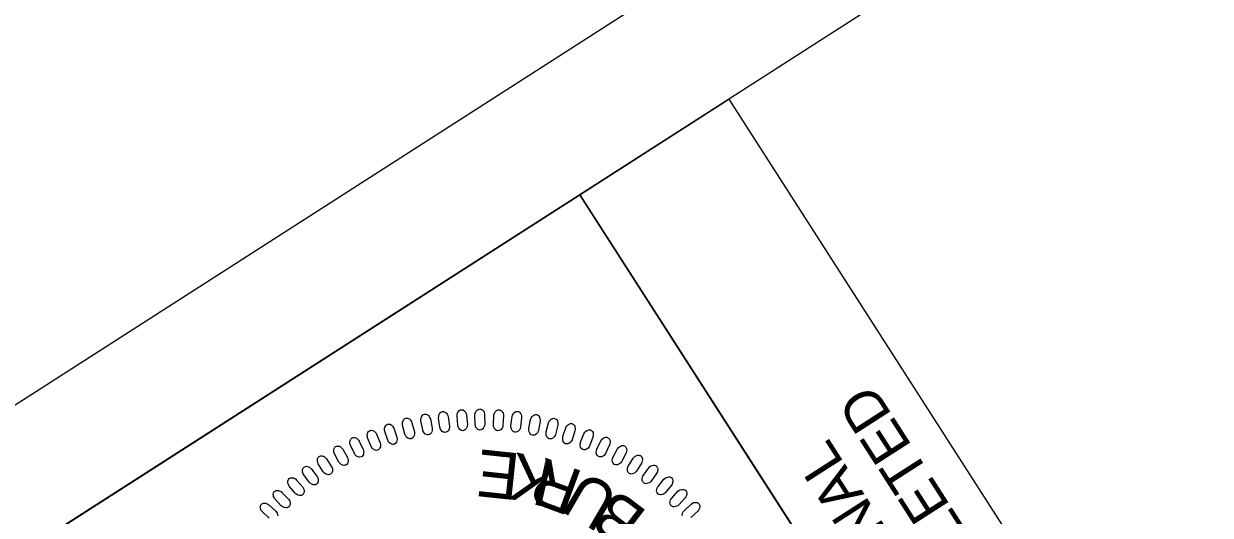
# Model space of a CAD drawing. Extents: x 476646 to 478477, y 498681 to 500689.
# Drawn here: x 476726.9 to 476884.6, y 500134.4 to 500199.8 of the extents above; entities that cross this region are included whole.
import ezdxf

# ---------------------------------------------------------------- set-up
doc = ezdxf.new("R2010")
doc.units = 0
for name, color, linetype in [('Sheet PE Seal Cell', 7, 'Continuous'), ('Sheet Plan CELL', 7, 'Continuous'), ('Sheet Plot Border Outside CELL', 7, 'Continuous'), ('Sheet Sticker Exception Certification CELL', 7, 'Continuous')]:
    doc.layers.add(name, color=color, linetype=linetype)

msp = doc.modelspace()

# ---------------------------------------------------------------- linework, layer by layer
at = {"layer": 'Sheet PE Seal Cell'}
for points in [[(476779.95, 500145.79), (476779.71, 500146.99), (476779.71, 500147.22), (476779.73, 500147.36), (476779.81, 500147.55), (476779.88, 500147.68), (476779.98, 500147.78), (476780.07, 500147.84), (476780.18, 500147.88), (476780.29, 500147.88), (476780.42, 500147.87), (476780.53, 500147.84), (476780.65, 500147.76), (476780.73, 500147.69), (476780.82, 500147.56), (476780.91, 500147.39), (476780.97, 500147.24), (476781.21, 500146.01), (476781.23, 500145.84), (476781.21, 500145.69), (476781.15, 500145.52), (476781.07, 500145.36), (476780.99, 500145.26), (476780.84, 500145.17), (476780.7, 500145.12), (476780.55, 500145.14), (476780.44, 500145.16), (476780.29, 500145.24), (476780.14, 500145.38), (476780.04, 500145.54), (476779.99, 500145.67)], [(476782.23, 500146.16), (476782.07, 500147.37), (476782.08, 500147.6), (476782.11, 500147.74), (476782.2, 500147.92), (476782.28, 500148.05), (476782.38, 500148.14), (476782.48, 500148.19), (476782.59, 500148.23), (476782.7, 500148.22), (476782.83, 500148.21), (476782.94, 500148.16), (476783.05, 500148.08), (476783.12, 500148), (476783.21, 500147.87), (476783.29, 500147.69), (476783.34, 500147.54), (476783.51, 500146.29), (476783.51, 500146.12), (476783.48, 500145.98), (476783.41, 500145.81), (476783.32, 500145.66), (476783.23, 500145.56), (476783.08, 500145.49), (476782.94, 500145.45), (476782.79, 500145.47), (476782.67, 500145.5), (476782.54, 500145.58), (476782.4, 500145.74), (476782.31, 500145.91), (476782.26, 500146.03)], [(476784.6, 500146.43), (476784.52, 500147.66), (476784.54, 500147.88), (476784.58, 500148.02), (476784.68, 500148.2), (476784.77, 500148.32), (476784.88, 500148.4), (476784.98, 500148.45), (476785.09, 500148.48), (476785.21, 500148.46), (476785.33, 500148.44), (476785.43, 500148.39), (476785.55, 500148.3), (476785.61, 500148.22), (476785.69, 500148.08), (476785.76, 500147.9), (476785.79, 500147.74), (476785.89, 500146.49), (476785.88, 500146.32), (476785.84, 500146.18), (476785.76, 500146.01), (476785.66, 500145.87), (476785.57, 500145.78), (476785.42, 500145.71), (476785.27, 500145.68), (476785.11, 500145.71), (476785.01, 500145.75), (476784.87, 500145.84), (476784.74, 500146), (476784.66, 500146.18), (476784.62, 500146.31)], [(476786.91, 500146.56), (476786.9, 500147.79), (476786.94, 500148.01), (476786.99, 500148.15), (476787.1, 500148.32), (476787.2, 500148.43), (476787.31, 500148.51), (476787.42, 500148.55), (476787.53, 500148.57), (476787.64, 500148.55), (476787.76, 500148.52), (476787.86, 500148.46), (476787.97, 500148.36), (476788.03, 500148.28), (476788.1, 500148.13), (476788.16, 500147.96), (476788.18, 500147.8), (476788.19, 500146.54), (476788.17, 500146.37), (476788.13, 500146.23), (476788.04, 500146.07), (476787.93, 500145.93), (476787.83, 500145.85), (476787.67, 500145.79), (476787.52, 500145.77), (476787.38, 500145.81), (476787.27, 500145.86), (476787.14, 500145.96), (476787.02, 500146.13), (476786.95, 500146.31), (476786.92, 500146.43)], [(476789.34, 500146.51), (476789.41, 500147.73), (476789.46, 500147.95), (476789.52, 500148.08), (476789.64, 500148.25), (476789.75, 500148.35), (476789.86, 500148.42), (476789.97, 500148.46), (476790.08, 500148.47), (476790.19, 500148.44), (476790.31, 500148.41), (476790.41, 500148.34), (476790.51, 500148.24), (476790.57, 500148.15), (476790.63, 500148), (476790.67, 500147.82), (476790.69, 500147.66), (476790.62, 500146.4), (476790.59, 500146.23), (476790.54, 500146.1), (476790.44, 500145.94), (476790.32, 500145.81), (476790.22, 500145.74), (476790.06, 500145.69), (476789.91, 500145.68), (476789.76, 500145.72), (476789.66, 500145.78), (476789.54, 500145.89), (476789.43, 500146.06), (476789.37, 500146.25), (476789.35, 500146.38)], [(476791.68, 500146.34), (476791.83, 500147.56), (476791.89, 500147.77), (476791.96, 500147.9), (476792.09, 500148.06), (476792.2, 500148.16), (476792.32, 500148.22), (476792.43, 500148.25), (476792.55, 500148.25), (476792.65, 500148.22), (476792.77, 500148.18), (476792.87, 500148.1), (476792.96, 500147.99), (476793.01, 500147.91), (476793.06, 500147.75), (476793.1, 500147.56), (476793.1, 500147.4), (476792.95, 500146.15), (476792.91, 500145.99), (476792.85, 500145.86), (476792.74, 500145.71), (476792.61, 500145.58), (476792.51, 500145.52), (476792.34, 500145.48), (476792.19, 500145.47), (476792.05, 500145.53), (476791.95, 500145.59), (476791.84, 500145.71), (476791.74, 500145.89), (476791.69, 500146.08), (476791.68, 500146.21)], [(476794.07, 500145.98), (476794.29, 500147.18), (476794.37, 500147.39), (476794.44, 500147.52), (476794.59, 500147.67), (476794.7, 500147.75), (476794.83, 500147.81), (476794.94, 500147.83), (476795.05, 500147.83), (476795.16, 500147.79), (476795.27, 500147.74), (476795.36, 500147.66), (476795.45, 500147.55), (476795.49, 500147.46), (476795.53, 500147.3), (476795.55, 500147.11), (476795.55, 500146.95), (476795.32, 500145.71), (476795.27, 500145.55), (476795.2, 500145.42), (476795.08, 500145.28), (476794.95, 500145.16), (476794.84, 500145.1), (476794.67, 500145.07), (476794.52, 500145.08), (476794.38, 500145.15), (476794.29, 500145.21), (476794.18, 500145.34), (476794.1, 500145.52), (476794.06, 500145.71), (476794.06, 500145.85)], [(476775.3, 500144.44), (476774.91, 500145.6), (476774.88, 500145.82), (476774.88, 500145.97), (476774.94, 500146.17), (476775, 500146.3), (476775.08, 500146.41), (476775.16, 500146.48), (476775.26, 500146.54), (476775.38, 500146.55), (476775.5, 500146.56), (476775.62, 500146.54), (476775.75, 500146.48), (476775.83, 500146.42), (476775.94, 500146.3), (476776.05, 500146.15), (476776.13, 500146), (476776.53, 500144.81), (476776.56, 500144.64), (476776.56, 500144.5), (476776.52, 500144.32), (476776.46, 500144.15), (476776.39, 500144.04), (476776.26, 500143.94), (476776.13, 500143.87), (476775.97, 500143.86), (476775.86, 500143.88), (476775.71, 500143.93), (476775.54, 500144.06), (476775.42, 500144.21), (476775.35, 500144.32)], [(476777.6, 500145.23), (476777.29, 500146.42), (476777.27, 500146.64), (476777.28, 500146.79), (476777.35, 500146.98), (476777.41, 500147.11), (476777.5, 500147.22), (476777.59, 500147.29), (476777.7, 500147.33), (476777.81, 500147.34), (476777.93, 500147.34), (476778.05, 500147.31), (476778.18, 500147.24), (476778.25, 500147.18), (476778.36, 500147.05), (476778.46, 500146.89), (476778.52, 500146.74), (476778.85, 500145.53), (476778.87, 500145.36), (476778.86, 500145.21), (476778.82, 500145.04), (476778.74, 500144.87), (476778.67, 500144.77), (476778.53, 500144.67), (476778.39, 500144.62), (476778.24, 500144.62), (476778.12, 500144.64), (476777.98, 500144.7), (476777.82, 500144.84), (476777.71, 500145), (476777.64, 500145.11)], [(476796.36, 500145.53), (476796.66, 500146.72), (476796.75, 500146.93), (476796.84, 500147.05), (476796.99, 500147.19), (476797.11, 500147.27), (476797.24, 500147.32), (476797.35, 500147.33), (476797.46, 500147.32), (476797.57, 500147.28), (476797.67, 500147.22), (476797.76, 500147.14), (476797.84, 500147.01), (476797.88, 500146.92), (476797.9, 500146.76), (476797.92, 500146.57), (476797.9, 500146.41), (476797.6, 500145.19), (476797.54, 500145.03), (476797.46, 500144.91), (476797.34, 500144.77), (476797.19, 500144.67), (476797.08, 500144.61), (476796.91, 500144.59), (476796.76, 500144.61), (476796.63, 500144.69), (476796.54, 500144.76), (476796.44, 500144.89), (476796.36, 500145.08), (476796.34, 500145.27), (476796.35, 500145.4)], [(476798.59, 500144.9), (476798.96, 500146.07), (476799.06, 500146.27), (476799.15, 500146.38), (476799.31, 500146.51), (476799.44, 500146.59), (476799.57, 500146.63), (476799.68, 500146.63), (476799.79, 500146.62), (476799.89, 500146.57), (476800, 500146.5), (476800.08, 500146.41), (476800.15, 500146.29), (476800.18, 500146.19), (476800.2, 500146.03), (476800.2, 500145.84), (476800.18, 500145.68), (476799.8, 500144.48), (476799.73, 500144.33), (476799.64, 500144.21), (476799.51, 500144.08), (476799.36, 500143.98), (476799.24, 500143.94), (476799.07, 500143.93), (476798.93, 500143.95), (476798.8, 500144.04), (476798.71, 500144.12), (476798.62, 500144.25), (476798.56, 500144.45), (476798.55, 500144.64), (476798.56, 500144.77)], [(476770.88, 500142.65), (476770.35, 500143.75), (476770.29, 500143.97), (476770.28, 500144.12), (476770.3, 500144.32), (476770.35, 500144.46), (476770.41, 500144.58), (476770.49, 500144.66), (476770.58, 500144.73), (476770.69, 500144.76), (476770.81, 500144.78), (476770.93, 500144.77), (476771.07, 500144.73), (476771.16, 500144.68), (476771.28, 500144.57), (476771.41, 500144.44), (476771.5, 500144.3), (476772.05, 500143.17), (476772.1, 500143.01), (476772.12, 500142.86), (476772.11, 500142.68), (476772.07, 500142.51), (476772.02, 500142.39), (476771.9, 500142.27), (476771.77, 500142.19), (476771.62, 500142.16), (476771.51, 500142.16), (476771.35, 500142.2), (476771.17, 500142.3), (476771.03, 500142.43), (476770.95, 500142.54)], [(476773.1, 500143.6), (476772.64, 500144.74), (476772.6, 500144.96), (476772.59, 500145.11), (476772.63, 500145.31), (476772.68, 500145.44), (476772.76, 500145.56), (476772.84, 500145.64), (476772.94, 500145.7), (476773.05, 500145.72), (476773.17, 500145.74), (476773.29, 500145.72), (476773.42, 500145.67), (476773.51, 500145.61), (476773.63, 500145.5), (476773.75, 500145.36), (476773.83, 500145.22), (476774.31, 500144.05), (476774.35, 500143.89), (476774.36, 500143.74), (476774.33, 500143.56), (476774.28, 500143.39), (476774.22, 500143.28), (476774.1, 500143.16), (476773.97, 500143.09), (476773.81, 500143.07), (476773.7, 500143.08), (476773.54, 500143.12), (476773.37, 500143.24), (476773.24, 500143.38), (476773.16, 500143.49)], [(476800.93, 500144.14), (476801.38, 500145.28), (476801.49, 500145.48), (476801.59, 500145.59), (476801.76, 500145.7), (476801.89, 500145.77), (476802.02, 500145.8), (476802.14, 500145.8), (476802.25, 500145.78), (476802.34, 500145.72), (476802.44, 500145.65), (476802.52, 500145.56), (476802.58, 500145.43), (476802.61, 500145.33), (476802.62, 500145.17), (476802.61, 500144.98), (476802.57, 500144.82), (476802.12, 500143.65), (476802.04, 500143.5), (476801.94, 500143.38), (476801.8, 500143.27), (476801.65, 500143.18), (476801.53, 500143.14), (476801.36, 500143.14), (476801.21, 500143.18), (476801.09, 500143.27), (476801.01, 500143.35), (476800.93, 500143.49), (476800.88, 500143.69), (476800.88, 500143.88), (476800.9, 500144.02)], [(476803.1, 500143.22), (476803.62, 500144.34), (476803.74, 500144.52), (476803.85, 500144.62), (476804.02, 500144.73), (476804.16, 500144.79), (476804.29, 500144.81), (476804.4, 500144.81), (476804.52, 500144.78), (476804.61, 500144.71), (476804.7, 500144.63), (476804.77, 500144.54), (476804.83, 500144.4), (476804.85, 500144.3), (476804.85, 500144.14), (476804.82, 500143.95), (476804.78, 500143.8), (476804.25, 500142.65), (476804.16, 500142.51), (476804.06, 500142.4), (476803.91, 500142.3), (476803.75, 500142.22), (476803.63, 500142.19), (476803.46, 500142.2), (476803.32, 500142.24), (476803.2, 500142.34), (476803.13, 500142.43), (476803.05, 500142.57), (476803.02, 500142.78), (476803.03, 500142.97), (476803.06, 500143.1)], [(476768.82, 500141.52), (476768.22, 500142.6), (476768.15, 500142.81), (476768.13, 500142.95), (476768.14, 500143.16), (476768.17, 500143.3), (476768.23, 500143.42), (476768.3, 500143.51), (476768.39, 500143.58), (476768.5, 500143.62), (476768.62, 500143.65), (476768.74, 500143.65), (476768.88, 500143.61), (476768.97, 500143.57), (476769.1, 500143.47), (476769.24, 500143.34), (476769.34, 500143.22), (476769.96, 500142.12), (476770.02, 500141.96), (476770.05, 500141.82), (476770.05, 500141.64), (476770.02, 500141.46), (476769.97, 500141.34), (476769.86, 500141.21), (476769.74, 500141.12), (476769.59, 500141.09), (476769.48, 500141.08), (476769.32, 500141.1), (476769.13, 500141.19), (476768.98, 500141.32), (476768.89, 500141.42)], [(476805.25, 500142.2), (476805.83, 500143.28), (476805.97, 500143.45), (476806.08, 500143.55), (476806.26, 500143.65), (476806.4, 500143.7), (476806.54, 500143.71), (476806.65, 500143.7), (476806.76, 500143.66), (476806.85, 500143.59), (476806.94, 500143.51), (476807, 500143.41), (476807.04, 500143.27), (476807.06, 500143.17), (476807.05, 500143.01), (476807.01, 500142.82), (476806.96, 500142.67), (476806.36, 500141.56), (476806.26, 500141.42), (476806.16, 500141.32), (476806, 500141.23), (476805.84, 500141.16), (476805.71, 500141.13), (476805.55, 500141.15), (476805.4, 500141.21), (476805.29, 500141.32), (476805.22, 500141.41), (476805.16, 500141.56), (476805.14, 500141.76), (476805.16, 500141.95), (476805.2, 500142.08)], [(476766.75, 500140.23), (476766.08, 500141.27), (476766, 500141.47), (476765.97, 500141.62), (476765.97, 500141.82), (476765.99, 500141.97), (476766.04, 500142.09), (476766.11, 500142.18), (476766.19, 500142.26), (476766.3, 500142.3), (476766.42, 500142.34), (476766.54, 500142.35), (476766.68, 500142.32), (476766.77, 500142.29), (476766.91, 500142.2), (476767.06, 500142.08), (476767.16, 500141.96), (476767.85, 500140.9), (476767.92, 500140.75), (476767.95, 500140.61), (476767.97, 500140.42), (476767.95, 500140.25), (476767.91, 500140.13), (476767.81, 500139.99), (476767.69, 500139.89), (476767.55, 500139.85), (476767.43, 500139.83), (476767.27, 500139.85), (476767.08, 500139.92), (476766.92, 500140.04), (476766.83, 500140.13)], [(476807.28, 500141.01), (476807.93, 500142.05), (476808.08, 500142.21), (476808.2, 500142.3), (476808.38, 500142.39), (476808.52, 500142.43), (476808.66, 500142.44), (476808.77, 500142.41), (476808.88, 500142.37), (476808.96, 500142.29), (476809.05, 500142.21), (476809.1, 500142.1), (476809.14, 500141.96), (476809.15, 500141.86), (476809.12, 500141.7), (476809.08, 500141.51), (476809.01, 500141.37), (476808.35, 500140.3), (476808.24, 500140.17), (476808.13, 500140.07), (476807.97, 500139.99), (476807.8, 500139.93), (476807.67, 500139.91), (476807.51, 500139.94), (476807.37, 500140.01), (476807.27, 500140.12), (476807.21, 500140.22), (476807.15, 500140.37), (476807.14, 500140.58), (476807.18, 500140.76), (476807.22, 500140.89)], [(476764.87, 500138.85), (476764.14, 500139.84), (476764.04, 500140.04), (476764, 500140.18), (476763.99, 500140.38), (476764, 500140.53), (476764.05, 500140.66), (476764.11, 500140.75), (476764.19, 500140.84), (476764.29, 500140.89), (476764.4, 500140.93), (476764.52, 500140.95), (476764.67, 500140.93), (476764.76, 500140.9), (476764.9, 500140.82), (476765.06, 500140.71), (476765.17, 500140.59), (476765.92, 500139.59), (476766, 500139.44), (476766.05, 500139.3), (476766.07, 500139.12), (476766.06, 500138.94), (476766.03, 500138.81), (476765.94, 500138.67), (476765.83, 500138.57), (476765.69, 500138.51), (476765.57, 500138.49), (476765.41, 500138.5), (476765.22, 500138.56), (476765.05, 500138.67), (476764.95, 500138.75)], [(476809.27, 500139.76), (476809.99, 500140.76), (476810.15, 500140.91), (476810.27, 500141), (476810.46, 500141.07), (476810.61, 500141.1), (476810.74, 500141.1), (476810.85, 500141.07), (476810.96, 500141.02), (476811.03, 500140.94), (476811.11, 500140.84), (476811.16, 500140.74), (476811.19, 500140.59), (476811.19, 500140.49), (476811.16, 500140.33), (476811.1, 500140.15), (476811.03, 500140.01), (476810.3, 500138.99), (476810.18, 500138.86), (476810.07, 500138.77), (476809.9, 500138.7), (476809.73, 500138.65), (476809.6, 500138.64), (476809.44, 500138.68), (476809.31, 500138.76), (476809.21, 500138.87), (476809.15, 500138.98), (476809.11, 500139.13), (476809.11, 500139.34), (476809.16, 500139.52), (476809.21, 500139.65)], [(476811.23, 500138.29), (476812.01, 500139.24), (476812.18, 500139.39), (476812.31, 500139.46), (476812.5, 500139.52), (476812.65, 500139.55), (476812.79, 500139.54), (476812.89, 500139.5), (476812.99, 500139.45), (476813.07, 500139.36), (476813.14, 500139.26), (476813.18, 500139.15), (476813.2, 500139.01), (476813.2, 500138.91), (476813.15, 500138.75), (476813.08, 500138.57), (476813, 500138.43), (476812.21, 500137.46), (476812.09, 500137.34), (476811.96, 500137.26), (476811.79, 500137.19), (476811.62, 500137.16), (476811.49, 500137.16), (476811.33, 500137.21), (476811.2, 500137.29), (476811.11, 500137.41), (476811.06, 500137.52), (476811.03, 500137.68), (476811.04, 500137.88), (476811.11, 500138.07), (476811.16, 500138.19)], [(476763.01, 500137.37), (476762.22, 500138.31), (476762.11, 500138.5), (476762.06, 500138.64), (476762.04, 500138.84), (476762.04, 500138.99), (476762.07, 500139.12), (476762.13, 500139.22), (476762.2, 500139.31), (476762.3, 500139.37), (476762.41, 500139.42), (476762.53, 500139.44), (476762.68, 500139.43), (476762.77, 500139.41), (476762.92, 500139.34), (476763.08, 500139.24), (476763.2, 500139.13), (476764.01, 500138.17), (476764.1, 500138.02), (476764.16, 500137.89), (476764.19, 500137.71), (476764.2, 500137.53), (476764.17, 500137.41), (476764.09, 500137.26), (476763.99, 500137.15), (476763.85, 500137.08), (476763.74, 500137.05), (476763.57, 500137.05), (476763.37, 500137.1), (476763.21, 500137.2), (476763.1, 500137.28)], [(476761.17, 500135.72), (476760.32, 500136.61), (476760.2, 500136.79), (476760.14, 500136.93), (476760.11, 500137.13), (476760.1, 500137.27), (476760.13, 500137.41), (476760.18, 500137.51), (476760.24, 500137.6), (476760.34, 500137.66), (476760.45, 500137.73), (476760.56, 500137.75), (476760.71, 500137.75), (476760.81, 500137.74), (476760.96, 500137.67), (476761.13, 500137.59), (476761.25, 500137.49), (476762.12, 500136.58), (476762.22, 500136.44), (476762.29, 500136.31), (476762.33, 500136.13), (476762.35, 500135.95), (476762.33, 500135.83), (476762.26, 500135.67), (476762.16, 500135.56), (476762.03, 500135.48), (476761.92, 500135.45), (476761.75, 500135.43), (476761.55, 500135.47), (476761.38, 500135.56), (476761.27, 500135.63)], [(476813.04, 500136.73), (476813.87, 500137.63), (476814.05, 500137.76), (476814.18, 500137.83), (476814.38, 500137.88), (476814.53, 500137.89), (476814.66, 500137.87), (476814.77, 500137.83), (476814.86, 500137.77), (476814.93, 500137.68), (476815, 500137.57), (476815.03, 500137.46), (476815.04, 500137.31), (476815.03, 500137.22), (476814.98, 500137.06), (476814.9, 500136.89), (476814.81, 500136.76), (476813.96, 500135.83), (476813.83, 500135.72), (476813.7, 500135.65), (476813.52, 500135.59), (476813.35, 500135.57), (476813.22, 500135.58), (476813.07, 500135.64), (476812.94, 500135.73), (476812.86, 500135.86), (476812.82, 500135.97), (476812.79, 500136.13), (476812.82, 500136.33), (476812.89, 500136.51), (476812.96, 500136.62)]]:
    msp.add_lwpolyline(points, close=True, dxfattribs=at)
for points in [[(476759.55, 500134.07), (476758.65, 500134.91), (476758.51, 500135.08), (476758.45, 500135.21), (476758.4, 500135.41), (476758.38, 500135.56), (476758.4, 500135.7), (476758.44, 500135.8), (476758.51, 500135.89), (476758.6, 500135.96), (476758.7, 500136.03), (476758.82, 500136.07), (476758.96, 500136.07), (476759.06, 500136.06), (476759.21, 500136.01), (476759.39, 500135.93), (476759.52, 500135.84), (476760.44, 500134.99), (476760.55, 500134.86), (476760.62, 500134.73), (476760.68, 500134.56), (476760.71, 500134.38)], [(476814.46, 500134.35), (476814.44, 500134.51), (476814.48, 500134.71), (476814.57, 500134.88), (476814.64, 500134.99), (476814.72, 500135.09), (476815.62, 500135.94), (476815.8, 500136.06), (476815.94, 500136.12), (476816.14, 500136.16), (476816.28, 500136.16), (476816.42, 500136.13), (476816.52, 500136.09), (476816.61, 500136.02), (476816.67, 500135.92), (476816.73, 500135.82), (476816.76, 500135.7), (476816.76, 500135.55), (476816.75, 500135.46), (476816.68, 500135.3), (476816.59, 500135.14), (476816.49, 500135.01), (476815.59, 500134.14)]]:
    msp.add_lwpolyline(points, dxfattribs=at)
at = {"layer": 'Sheet Plan CELL'}
for points in [[(476674.53, 500096.04), (477484.51, 498833.48), (478368.28, 499400.46), (477558.31, 500662.99)], [(476760.16, 500032.13), (476706.16, 500116.28), (476800.85, 500177.05), (476854.86, 500092.89)]]:
    msp.add_lwpolyline(points, close=True, dxfattribs=at)
at = {"layer": 'Sheet Plot Border Outside CELL'}
msp.add_lwpolyline([(478477.12, 499272.48), (477568.08, 500689.45), (476646.44, 500098.18), (477555.48, 498681.21)], close=True, dxfattribs=at)
at = {"layer": 'Sheet Sticker Exception Certification CELL'}
for p, q in [((476800.85, 500177.05), (476820.63, 500189.74)), ((476800.85, 500177.05), (476820.63, 500189.74)), ((476820.62, 500189.73), (476928.63, 500021.36)), ((476820.62, 500189.73), (476928.63, 500021.36)), ((476908.85, 500008.67), (476800.84, 500177.04)), ((476908.85, 500008.67), (476800.84, 500177.04))]:
    msp.add_line(p, q, dxfattribs=at)

# ---------------------------------------------------------------- texts
at = {"layer": 'Sheet PE Seal Cell'}
for s, rotation, p in [('E', 173.9501, (476793.06, 500142.64)), ('K', 167.1044, (476797.74, 500141.59)), ('R', 159.8294, (476801.5, 500140.17)), ('U', 149.7295, (476806.39, 500137.48)), ('B', 142.6127, (476810, 500134.78))]:
    msp.add_text(s, height=6.24, rotation=rotation, dxfattribs=at).set_placement(p)
at = {"layer": 'Sheet Sticker Exception Certification CELL'}
for s, p in [('UNLESS ALL SIGNATURES COMPLETED', (476916.33, 500032.48)), ('UNLESS ALL SIGNATURES COMPLETED', (476916.33, 500032.48)), ('DOCUMENT NOT CONSIDERED FINAL', (476906.18, 500031.99)), ('DOCUMENT NOT CONSIDERED FINAL', (476906.18, 500031.99))]:
    msp.add_text(s, height=5.5, rotation=122.6818, dxfattribs=at).set_placement(p)

doc.saveas('drawing.dxf')
